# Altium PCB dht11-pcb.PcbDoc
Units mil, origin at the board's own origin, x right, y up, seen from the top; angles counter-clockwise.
Board outline 2115 x 2690 mil, 2 copper layers (Top Layer, Bottom Layer); 49 components, 31 nets, 189 pads, 153 vias.
Unrouted connection lines stored in the file: 35.
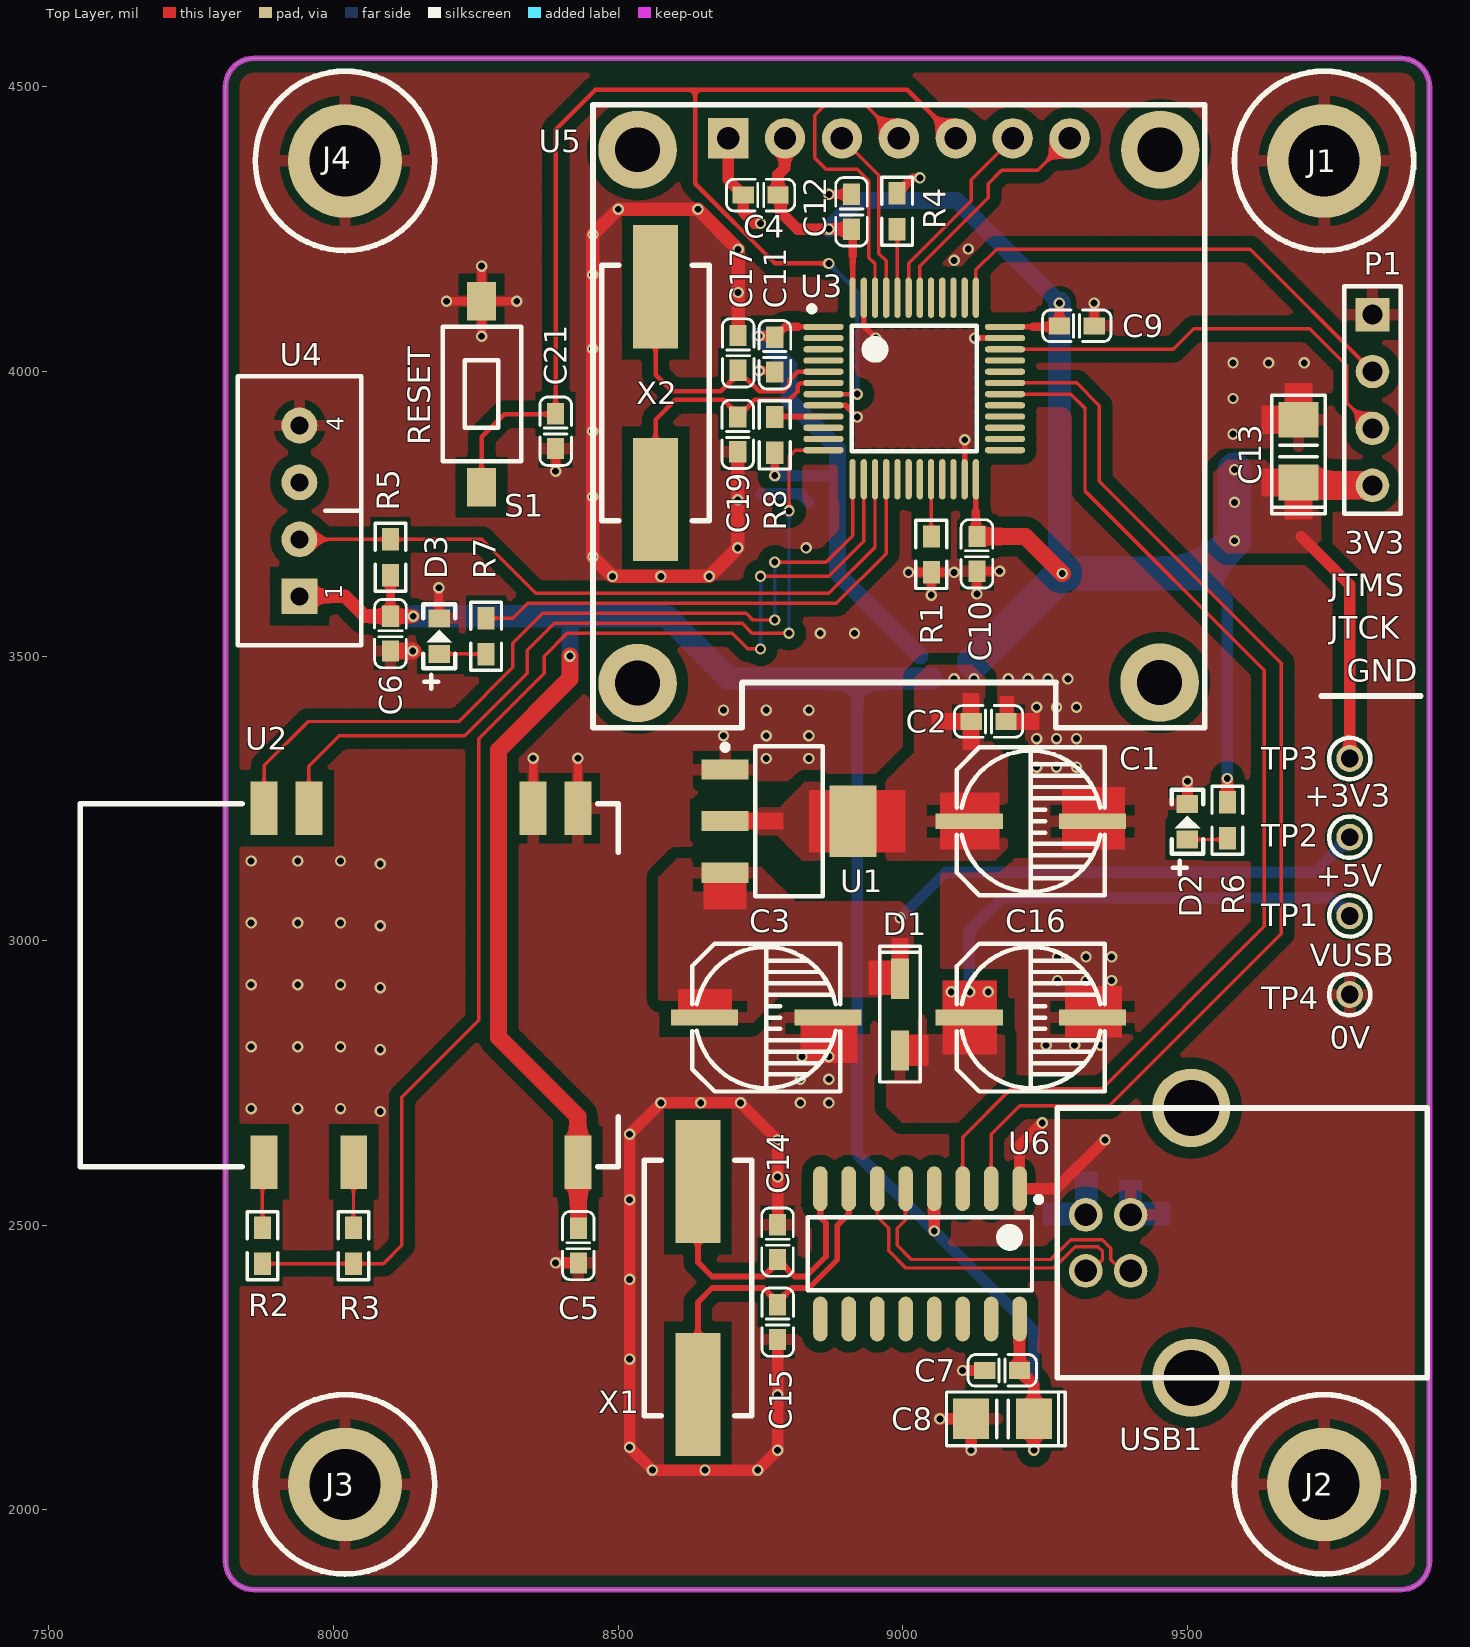
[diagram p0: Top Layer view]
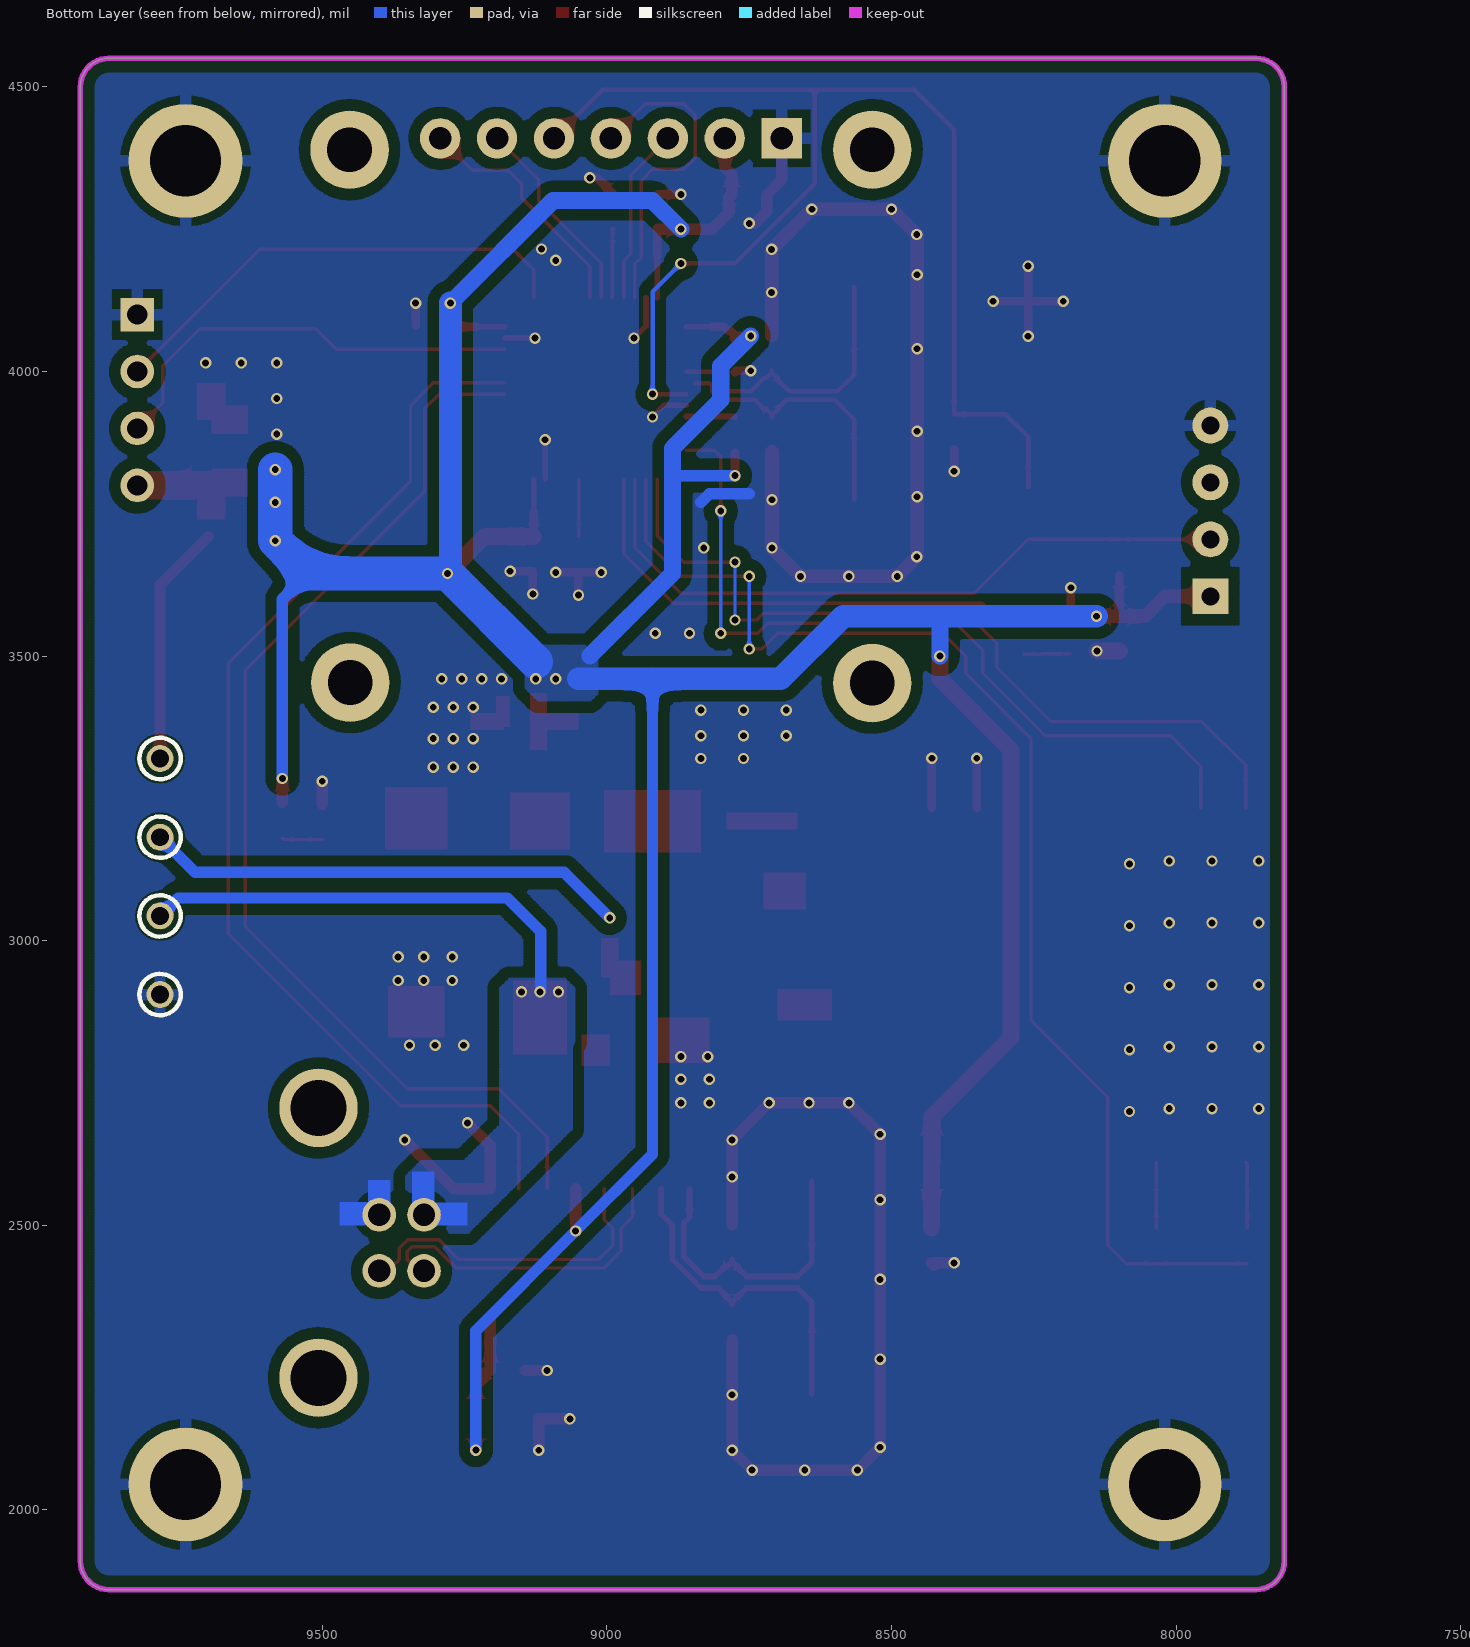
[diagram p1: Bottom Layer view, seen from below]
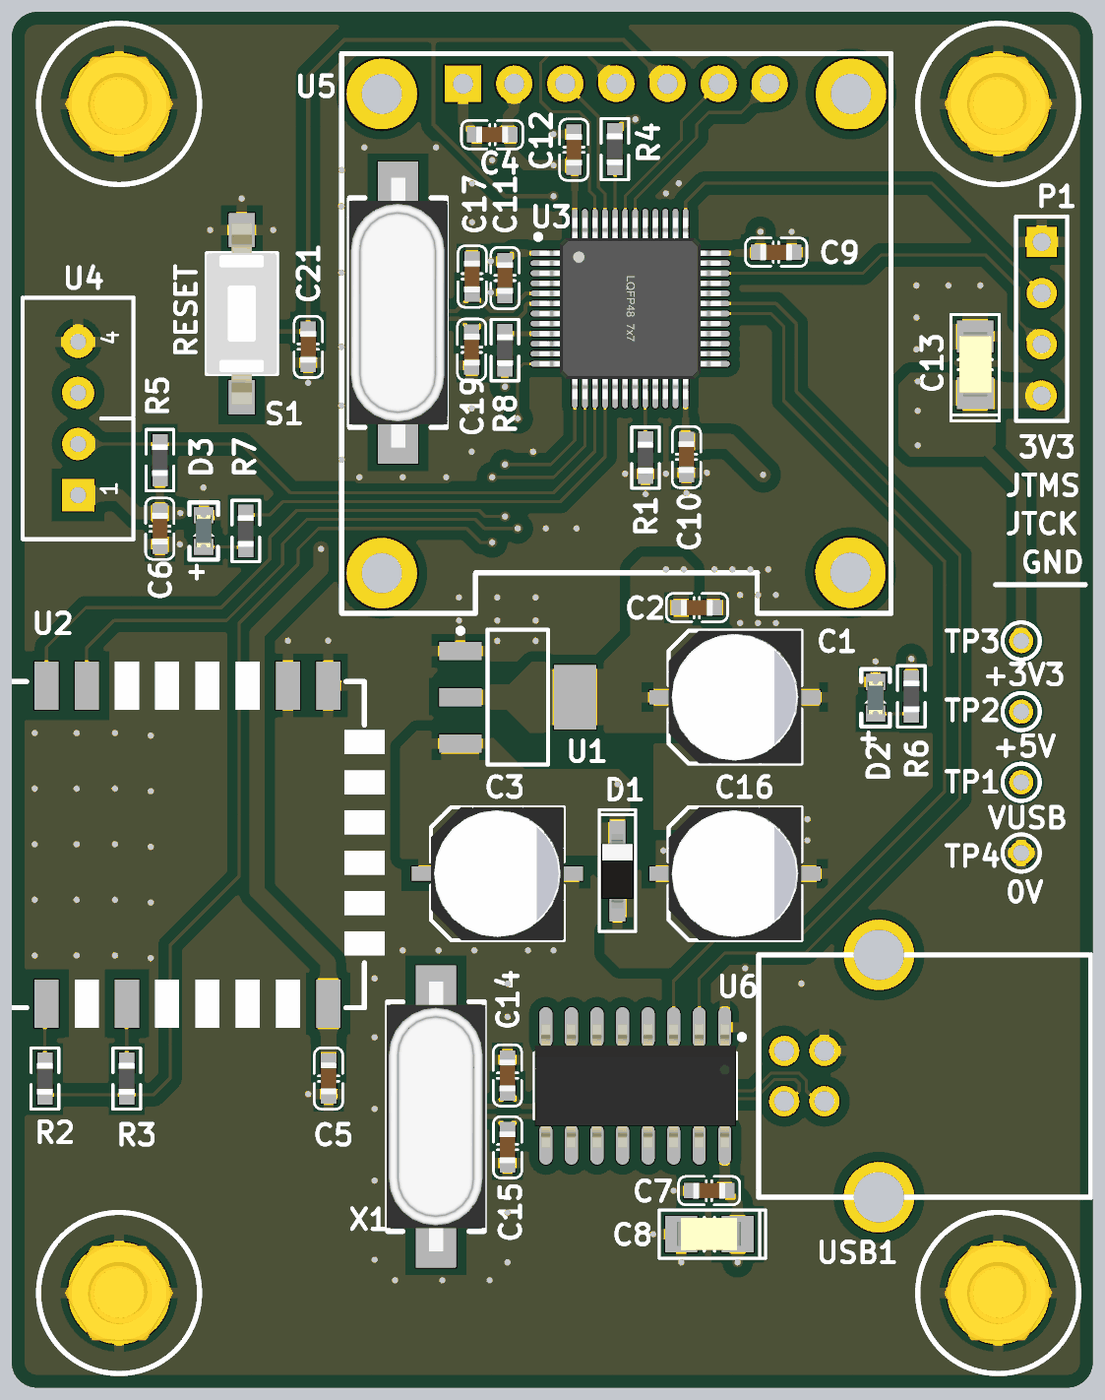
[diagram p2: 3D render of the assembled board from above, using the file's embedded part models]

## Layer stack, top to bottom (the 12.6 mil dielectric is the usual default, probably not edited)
Top Solder: solder mask 0.4, Solder Resist, Dk 3.5
Top Layer: signal copper 1.4
Dielectric 1: dielectric 12.6, FR-4, Dk 4.8
Bottom Layer: signal copper 1.4
Bottom Solder: solder mask 0.4, Solder Resist, Dk 3.5

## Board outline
7810,1910 7810,4500 cw(c7860,4500) 7860,4550 9875,4550 cw(c9875,4500) 9925,4500 9925,1910 cw(c9875,1910) 9875,1860 7860,1860 cw(c7860,1910)

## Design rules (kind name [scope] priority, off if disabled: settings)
Clearance [All] p1: gap=6 ignorepadtopadclearanceinfootprint=TRUE except(10: Arc-Via Track-Via SMDPad-Via THPad-Via Via-Via; 20: Arc-Fill Arc-Poly Arc-Region Track-Fill Track-Poly Track-Region SMDPad-Fill SMDPad-Poly SMDPad-Region THPad-Fill THPad-Poly THPad-Region Via-Fill Via-Poly Via-Region Fill-Fill Fill-Poly Fill-Region Poly-Poly Poly-Region Region-Region)
PolygonConnect PolygonConnect_via [isvia] p1: connectstyle=Direct reliefconductorwidth=10 reliefentries=4 polygonreliefangle="90 Angle" airgapwidth=10
PolygonConnect [All] p2: connectstyle=Relief reliefconductorwidth=20 reliefentries=4 polygonreliefangle="90 Angle" airgapwidth=15
RoutingVias [All] p1: holewidth=12 width=24 viastyle="Through Hole" minholewidth=12 minwidth=24 maxholewidth=12 maxwidth=24
SolderMaskExpansion [All] p1: expansion=2.5
Width Width_POWER [InNetClass('POWER')] p1: maxlimit=60 minlimit=10 preferedwidth=15
Width [All] p2: maxlimit=10 minlimit=6 preferedwidth=6
30 further rules are at their usual default settings.

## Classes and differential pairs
net class MISC: LED0 NetC14_2 NetC15_2 NetD2_1 NetD3_1 NetR1_1 NetR2_2 NetR3_2 NetR4_1 NetR8_2 PA5/DATA WIFI_EN
net class USART: PA2/USART2_TXD PA3/USART2_RXD PA9/USART1_TXD PA10/USART1_RXD
net class OLED: OLED_CS OLED_D0 OLED_D1 OLED_DC
net class POWER: GND VCC_3V3 VCC_5V VCC_USB

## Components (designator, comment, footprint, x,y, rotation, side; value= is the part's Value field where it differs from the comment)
C1 "220uF" C_SMD(6.3x5.3) 9225,3210 r0 top
C2 "0.1uF" C0603 9150.51,3385 r180 top
C3 "220uF/10V" C_SMD(6.3x5.3) 8760,2865 r0 top
C4 "0.1uF" C0603 8750,4310 r0 top
C5 "0.1uF" C0603 8430,2464.49 r270 top
C6 "0.1uF" C0603 8100,3539.49 r270 top
C7 "0.1uF" C0603 9174.49,2245 r180 top
C8 "10uF" TAC1206 9175,2160 r180 top
C9 "0.1uF" C0603 9305.51,4080 r180 top
C10 "0.1uF" C0603 9130,3679.49 r90 top
C11 "0.1uF" C0603 8775,4029.49 r90 top
C12 "0.1uF" C0603 8910,4280.51 r270 top
C13 "10uF" TAC1206 9695,3860 r90 top
C14 "22pF" C0603 8780.02,2470.47 r270 top
C15 "22pF" C0603 8780.02,2329.96 r90 top
C16 "220uF/10V" C_SMD(6.3x5.3) 9225,2865 r0 top
C17 "22pF" C0603 8710.62,4032.46 r90 top
C19 "22pF" C0603 8710,3889.49 r270 top
C21 "0.1uF" C0603 8390,3895 r90 top
D1 "1N5819" SOD123 8995,2870 r90 top
D2 "LED" LED_0603 9500,3208.9 r90 top
D3 "LED" LED_0603 8185.69,3535 r90 top
J1 "Hole-3mmx6mm" M3x7+6_L 9740,4370 r0 top
J2 "Hole-3mmx6mm" M3x7+6_L 9740,2045 r0 top
J3 "Hole-3mmx6mm" M3x7+6_L 8020,2045 r0 top
J4 "Hole-3mmx6mm" M3x7+6_L 8020,4370 r0 top
P1 "Download" HDR1X4 9825,4099.88 r270 top
R1 "10K" R0603 9050,3678.5 r270 top
R2 "1K" R0603 7875,2464.19 r90 top
R3 "1K" R0603 8035,2464.19 r90 top
R4 "10K" R0603 8990,4281.5 r90 top
R5 "4K7" R0603 8100,3673.5 r270 top
R6 "1K" R0603 9570,3211.5 r270 top
R7 "1K" R0603 8268,3535 r270 top
R8 "0R" R0603 8775,3888.5 r90 top
S1 "SW-PB" "micro button_2_SMD" 8260,3960 r90 top
TP1 "VUSB" TP 9785,3043.56 r270 top
TP2 "+5V" TP 9785,3181.78 r270 top
TP3 "+3V3" TP 9785,3320 r270 top
TP4 "0V" TP 9785,2905.34 r270 top
U1 "AMS1117-3v3" SOT223_L 8800,3210 r0 top
U2 "ESP8266" ESP8266 8429.13,3240.59 r270 top
U3 "STM32F103C8T6" "LQFP48 7X7_N" 9020,3970 r270 top
U4 "DHT11" DHT11 7940,3755 r90 top
U5 "OLED_0R96" OLED_0.96_SPI 8993,3931 r0 top locked
U6 "CH340" SOIC_16 9030,2450 r270 top
USB1 "USB-B" USB-B 9321.26,2420 r90 top
X1 "12MHz" HC-49SMD 8640,2390 r90 top
X2 "8MHz" HC-49SMD 8565.62,3961.95 r90 top

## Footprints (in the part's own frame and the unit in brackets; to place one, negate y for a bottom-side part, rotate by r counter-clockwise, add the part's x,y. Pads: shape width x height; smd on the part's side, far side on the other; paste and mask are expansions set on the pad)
C0603 [mm] "Chip Capacitor, 2-Leads, Body 1.6x0.8mm, IPC Medium Density"
  rect 0.95x0.762 smd: 1(-0.775,0) 2(0.775,0)
  silkscreen extent -1.53,-0.71 1.53,0.7, body extent -0.8,-0.4 0.8,0.4, height 0.6
C_SMD(6.3x5.3) [mm]
  rect 3x0.7 smd: 1(-2.75,0) 2(2.75,0)
  silkscreen extent -3.3,-3.3 3.3,3.3, body extent -3.3,-3.3 3.3,3.3, height 5.42
DHT11 [mm]
  rect 1.6x1.6 hole 0.8: 1(-3.81,0)
  round 1.6 hole 0.8: 2(-1.27,0) 3(1.27,0) 4(3.81,0)
  silkscreen extent -6,-2.75 6,2.75
ESP8266 [mm]
  rect 2.4x1.2 smd: 1(0.2,0) 2(0.2,-2) 7(0.2,-12) 8(0.2,-14) 9(16,-14) 11(16,-10) 16(16,0)
  rect 2.4x1.2 on Top Overlay: 3(0.2,-4) 4(0.2,-6) 5(0.2,-8) 6(0.2,-10) 10(16,-12) 12(16,-8) 13(16,-6) 14(16,-4) 15(16,-2)
  rect 1.2x2 on Top Overlay: 17(13,1.8) 18(11,1.8) 19(9,1.8) 20(7,1.8) 21(5,1.8) 22(3,1.8)
  silkscreen extent 0,-22.2 16.2,1.8
HC-49SMD [mm]
  rect 5.5x2 smd: 1(-4.75,0) 2(4.75,0)
  silkscreen extent -5.7,-2.4 5.7,2.4, body extent -6.7,-2.46 6.7,2.44, height 4
HDR1X4 [mm] "Connector; Header; 4 Position"
  rect 1.5x1.5 hole 0.9: 1(0,0)
  round 1.5 hole 0.9: 2(2.54,0) 3(5.08,0) 4(7.62,0)
  silkscreen extent -1.27,-1.27 8.89,1.27
LED_0603 [mm]
  rect 0.8x0.96 smd: 1(-0.79,0) 2(0.79,0)
  silkscreen extent -2.35,-0.71 1.42,0.71, body extent -0.81,-0.4 0.81,0.4, height 0.6
"LQFP48 7X7_N" [mm] "7*7*1.4(长宽高，除引脚）"
  oval 0.279x1.8 smd: 1(-2.75,-4.05) 2(-2.25,-4.05) 3(-1.75,-4.05) 4(-1.25,-4.05) 5(-0.75,-4.05) 6(-0.25,-4.05) 7(0.25,-4.05) 8(0.75,-4.05) 9(1.25,-4.05) 10(1.75,-4.05) 11(2.25,-4.05) 12(2.75,-4.05) 25(2.75,4.05) 26(2.25,4.05) 27(1.75,4.05) 28(1.25,4.05) 29(0.75,4.05) 30(0.25,4.05) 31(-0.25,4.05) 32(-0.75,4.05) 33(-1.25,4.05) 34(-1.75,4.05) 35(-2.25,4.05) 36(-2.75,4.05)
  oval 1.8x0.279 smd: 13(4.05,-2.75) 14(4.05,-2.25) 15(4.05,-1.75) 16(4.05,-1.25) 17(4.05,-0.75) 18(4.05,-0.25) 19(4.05,0.25) 20(4.05,0.75) 21(4.05,1.25) 22(4.05,1.75) 23(4.05,2.25) 24(4.05,2.75) 37(-4.05,2.75) 38(-4.05,2.25) 39(-4.05,1.75) 40(-4.05,1.25) 41(-4.05,0.75) 42(-4.05,0.25) 43(-4.05,-0.25) 44(-4.05,-0.75) 45(-4.05,-1.25) 46(-4.05,-1.75) 47(-4.05,-2.25) 48(-4.05,-2.75)
  silkscreen extent -3.68,-4.7 2.79,2.79, body extent -4.5,-4.5 4.5,4.5, height 1.45
M3x7+6_L [mil] "M3铜柱，长：7mm，螺纹长：6mm"
  round 200 hole 125: 1(0,0)
  silkscreen extent -157,-157 157,157, body extent -106,-93 106,93, height 278
"micro button_2_SMD" [mm]
  rect 1.7x1.3 smd: 1(-4.15,0) 2(4.15,0)
  silkscreen extent -3,-1.76 3,1.74, body extent -4.5,-1.75 4.5,1.75, height 4.51
OLED_0.96_SPI [mm] "GND、VCC、SCL、SDA"
  round 3.5 hole 2 mask+0.102: 0(-11.659,-12.154) 0(-11.659,11.646) 0(11.633,-12.128) 0(11.659,11.646)
  rect 1.8x1.8 hole 1 mask+0.102: 1(-7.62,12.154)
  round 1.8 hole 1 mask+0.102: 2(-5.08,12.154) 3(-2.54,12.154) 4(0,12.154) 5(2.54,12.154) 6(5.08,12.154) 7(7.62,12.154)
  silkscreen extent -13.65,-14.15 13.65,13.65
R0603 [mm] "Chip Resistor, 2-Leads, Body 1.6x0.8mm, IPC Medium Density"
  rect 1x0.762 smd: 1(-0.8,0) 2(0.8,0)
  silkscreen extent -1.52,-0.69 1.52,0.69, body extent -0.8,-0.4 0.8,0.4, height 0.38
SOD123 [mm]
  rect 1.8x0.8 smd: 1(-1.6,0) 2(1.6,0)
  silkscreen extent -3,-0.9 3.05,0.9, body extent -1.85,-0.8 1.85,0.8, height 1.27
SOIC_16 [mm]
  oval 2x0.65 smd: 1(-2.906,4.445) 2(-2.906,3.175) 3(-2.906,1.905) 4(-2.906,0.635) 5(-2.906,-0.635) 6(-2.906,-1.905) 7(-2.906,-3.175) 8(-2.906,-4.445) 9(2.906,-4.445) 10(2.906,-3.175) 11(2.906,-1.905) 12(2.906,-0.635) 13(2.906,0.635) 14(2.906,1.905) 15(2.906,3.175) 16(2.906,4.445)
  silkscreen extent -2.55,-5 1.63,5.42, body extent -3.06,-5 3.06,5, height 1.48
SOT223_L [mm] "SOT223, 4-Leads, Body 6.5x3.5mm, Pitch 2.3mm, Lead Span 7mm, IPC High Density"
  rect 2.1x0.9 smd: 1(-2.85,2.3) 2(-2.85,0) 3(-2.85,-2.3)
  rect 2.1x3.2 smd: 4(2.85,0)
  silkscreen extent -2.97,-3.35 1.5,3.42, body extent -1.85,-3.35 1.85,3.35, height 1.7
TAC1206 [mm]
  rect 1.6x1.8 smd: 1(-1.4,0) 2(1.4,0)
  silkscreen extent -2.79,-1.2 2.5,1.2, body extent -1.56,-0.81 1.61,0.79, height 1.77
TP [mm]
  round 1.2 hole 0.8: 1(0,0)
  silkscreen extent -0.92,-0.92 0.92,0.92
USB-B [mm]
  round 3.5 hole 2.5: 0(-4.77,-4.71) 0(7.27,-4.71)
  round 1.5 hole 1: 1(2.5,0) 2(0,0) 3(0,-2) 4(2.5,-2)
  silkscreen extent -4.77,-15.24 7.27,1.27

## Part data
C1 C3 C16: library part Cap3, "CAP ALUM POLY 150UF 20% 10V SMD", ESR (Equivalent Series Resistance)="22 mOhm", Lifetime @ Temp.="2000 Hrs @ 105°C", Manufacturer=KEMET, Manufacturer Part Number=A765EB157M1ALAE022, Operating Temperature="-55°C ~ 105°C", Package / Case="Radial, Can - SMD", Ratings=-, Supplier Part Number 1=399-13671-1-ND, Tolerance=±20%
C2 C4 C5 C6 C7 C9 C10 C11 C12 C14 C15 C17 C19 C21: library part Cap1, "CAP CER 10000PF 100V X7R 0603", Manufacturer="TDK Corporation", Manufacturer Part Number=C1608X7R2A103K080AA, Operating Temperature="-55°C ~ 125°C", Package / Case="0603 (1608 Metric)", Ratings=-, Supplier Part Number 1=445-1304-2-ND, Temperature Coefficient=X7R, Tolerance=±10%, Voltage - Rated=100V
C8 C13: library part Cap2, "CAP TANT 10UF 10V 10% 1206", ESR (Equivalent Series Resistance)="3.8 Ohm", Lifetime @ Temp.="2000 Hrs @ 125°C", Manufacturer=KEMET, Manufacturer Part Number=T491A106K010AT7280, Manufacturer Size Code=A, Operating Temperature="-55°C ~ 125°C", Package / Case="1206 (3216 Metric)", Supplier Part Number 1=399-8268-2-ND, Tolerance=±10%
D1: library part Diode, "Default Diode"
D2 D3: "Typical RED GaAs LED"
J1 J2 J3 J4: library part HOLED
P1 USB1: library part "Header 4", "Header, 4-Pin"
R1 R2 R3 R4 R5 R6 R7 R8: library part R, "贴片电阻"
S1: "Switch"
TP1 TP2 TP3: library part TP+, "正测试环"
TP4: library part TP-, "负测试环"
U2: library part "ESP8266 Module"
U3: "ARM Cortex-M3 32-bit MCU, 64 KB Flash, 20 KB Internal RAM, 37 I/Os, 48-pin LQFP, -40 to 85 degC, Tray", I/Os (High Current)=37, Operating Frequency(F) (Processor speed) (MHz)=72, Supplier Part Number 1=497-6063-ND, Supply Voltage(Vcc) min (V)=2
U4: "GROVE TEMP/HUMIDITY SENSOR", Manufacturer="Seeed Technology Co., Ltd", Manufacturer Part Number=101020011, Supplier Part Number 1=1597-1124-ND
U5: library part OLED_7P_0R96
X1 X2: library part Crystal, "CRYSTAL 12.0000MHZ 18PF SMD", Frequency Stability=±50ppm, Frequency Tolerance=±20ppm, Load Capacitance=18pF, Manufacturer="Abracon LLC", Manufacturer Part Number=ABLS-12.000MHZ-B2-T, Operating Mode=Fundamental, Operating Temperature="-20°C ~ 70°C", Package / Case=HC-49/US, Ratings=-, Supplier Part Number 1=535-9067-2-ND

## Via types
v1: diameter 20, hole 12, Top Layer to Bottom Layer, tented both sides, 153 vias

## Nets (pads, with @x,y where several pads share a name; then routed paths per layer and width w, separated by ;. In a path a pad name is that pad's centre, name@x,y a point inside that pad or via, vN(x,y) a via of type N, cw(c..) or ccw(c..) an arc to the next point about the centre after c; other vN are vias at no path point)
D+: U6.5 USB1.3 | length 575
  Top Layer w6: U6.5 9005,2510 8990,2495 8990,2465 9015,2440 9260,2440 9295,2475 9350,2475 9365,2460 9365,2440 9371.26,2433.74 9371.9,2433.74 9385.64,2420 USB1.3
D-: U6.6 USB1.2 | length 576.9
  Top Layer w6: U6.6 8955,2515 8975,2495 8975,2455 9005,2425 9265,2425 9302.5,2462.5 9342.5,2462.5 9350.78,2454.22 9350.78,2440 9330.78,2420 USB1.2
GND: C1.2 C2.1 C3.2 C4.1 C5.2 C6.2 C7.2 C8.2 C9.1 C10.1 C11.1 C12.1 C13.2 C14.1 C15.1 C16.2 C17.2 C19.2 C21.1 D2.2 D3.2 J1.1 J2.1 J3.1 J4.1 P1.1 R1.2 R4.2 S1.2 TP4.1 U1.1 U2.1 U2.2 U3.8 U3.23 U3.35 U3.47 U4.4 U5.1 U6.1 USB1.4 | length 4966.8
  Top Layer w10: U3.8 8899.53,3940.47 v1(8920,3920) ; U3.47 8931.42,4079.67 v1(8952.5,4058.58) ; U3.23 v1(9108.58,3880) ; v1(9126.42,4058.58) U3.35
  Top Layer w15: v1(8185,3620) 8185,3566.79 D3.2 ; v1(8198.39,4123.39) S1.2 ; v1(8260,4061.77) S1.2 ; v1(8260,4185) S1.2 ; v1(8321.61,4123.39) S1.2 ; U2.2 v1(8350.39,3320.39) ; v1(8390,3824.53) C21.1@8390,3863.5 ; U2.1 v1(8429.13,3320.39) ; v1(8747.44,4001.25) 8772.73,4001.25 C11.1 ; v1(8870,4311.02) C12.1 ; R4.2 9017.01,4340 v1(9030,4340) ; v1(9010,3647.01) R1.2 ; v1(9050,3607.01) R1.2 ; v1(9090,3647.01) R1.2 ; v1(9130,3608.98) C10.1 v1(9170,3648.98) ; C9.1 v1(9336.02,4120)
  Top Layer w20: v1(8390,2433.98) C5.2 C5.2@8426.02,2430 ; U5.1 8693,4336.49 C4.1@8710.79,4318.7 ; C4.1 8719.49,4280.51 8740,4260 v1(8750,4260) ; C15.1 v1(8780.02,2105.02) v1(8745,2070) v1(8560,2070) v1(8520,2110) v1(8520,2660) v1(8575,2715) v1(8715,2715) v1(8780.02,2649.98) C14.1 ; v1(9065,2160) C8.2 ; v1(9105,2245) C7.2 ; v1(9119.88,2105) C8.2@9119.88,2159.88 ; v1(9245,2680) 9205,2640 U6.1 9269.43,2564.43 v1(9355,2650) ; D2.2 v1(9500,3280)
  Top Layer w24: C19.2 v1(8710,3690) v1(8660,3640) v1(8490,3640) 8455,3675 8455,4240 v1(8500,4285) v1(8640,4285) v1(8710.62,4214.38) C17.2
  Top Layer w30: C6.2 v1(8138.98,3508.98)
  Bottom Layer w20: 8750,3785 8820,3785 8835,3770
  other v1: 8652.5,2070 8780.02,2202.23 8520,2265 8520,2405 8520,2545 8780,2585 8082.05,2700 7855,2705 7937.05,2705 8012.05,2705 8645,2715 8820,2715 8870,2715 8820,2756.46 8870,2756.46 8822.73,2796.46 8870,2796.46 8082.05,2808.75 7855,2813.75 7937.05,2813.75 8012.05,2813.75 9251.73,2816.46 9301.73,2816.46 9346.73,2816.46 8082.05,2917.5 7855,2922.5 7937.05,2922.5 8012.05,2922.5 9271.73,2930 9321.73,2930 9366.73,2930 9271.73,2971.46 9321.73,2971.46 9366.73,2971.46 8082.05,3026.25 7855,3031.25 7937.05,3031.25 8012.05,3031.25 8082.05,3135 7855,3140 7937.05,3140 8012.05,3140 9235,3305 9270,3305 9305,3305 8760,3320 8835,3320 9235,3355 9270,3355 9305,3355 8685,3360 8760,3360 8835,3360 8685,3405 8760,3405 8835,3405 9235,3410 9270,3410 9305,3410 9185,3460 9220,3460 9255,3460 9290,3460 8855,3540 8915,3540 8575,3640 8455.6,3674.4 8830,3690 8710,3774.49 8455,3780 9580,3890 8455,3895 9580,3952.5 9580,4015 9642.5,4015 9705,4015 8455,4040 8710.62,4138.68 8455,4170 9090,4195 9115,4215 8455.6,4240.6
JTCK: P1.2 U3.37 | length 849.9
  Top Layer w6: U3.37 9128.27,4178.27 9165,4215 9609.88,4215 P1.2
JTMS: P1.3 U3.34 | length 771.2
  Top Layer w6: U3.34 9475,4038.9 9511.1,4075 9715,4075 9779.94,4010.06 9779.94,3944.94 P1.3
LED0: R7.1 U3.16 | length 880.4
  Top Layer w6: R7.1 8315,3566.5 8341,3592.5 8883.29,3592.5 8970.79,3680 U3.16
NetC14_2: C14.2 U6.8 X1.2 | length 541.6
  Top Layer w10: X1.2 8640,2435 8665,2410 8755,2410 8770.02,2425.02 8770.02,2426.26 C14.2@8780.02,2436.26 ; C14.2 C14.2@8780.02,2436.26 ; U6.8 8855,2514 8865,2504 8865,2445 8830,2410 8809.98,2410 8793.72,2426.26 8790.02,2426.26 C14.2@8780.02,2436.26
NetC15_2: C15.2 U6.7 X1.1 | length 596.8
  Top Layer w10: X1.1 8640,2365 8665,2390 8755,2390 8770.02,2374.98 8770.02,2374.17 C15.2@8780.02,2364.17 ; C15.2 C15.2@8780.02,2364.17 ; U6.7 8905,2520 8885,2500 8885,2440 8835,2390 8805,2390 8790.02,2375.02 8790.02,2374.17 C15.2@8780.02,2364.17
NetD2_1: D2.1 R6.2 | length 70.9
  Top Layer w6: D2.1 9567.8,3177.8 R6.2
NetD3_1: D3.1 R7.2 | length 82.5
  Top Layer w6: D3.1 8236.2,3503.9 8236.59,3503.5 R7.2
NetR1_1: R1.1 U3.20 | length 100.7
  Top Layer w6: U3.20 9049.53,3710.47 R1.1
NetR2_2: R2.2 U2.9 | length 116.2
  Top Layer w6: R2.2 7875,2607.72 U2.9
NetR3_2: R3.2 U2.11 | length 115.2
  Top Layer w6: R3.2 8035,2610.24 U2.11
NetR4_1: R4.1 U3.44 | length 120.7
  Top Layer w6: U3.44 R4.1@8990.47,4249.53
  Top Layer w10: R4.1 R4.1@8990.47,4249.53
NetR8_2: R8.2 U3.9 | length 85.9
  Top Layer w10: R8.2 8775.79,3920.79 U3.9
NRST: C21.2 S1.1 U3.7 U5.5 | length 2269.9
  Top Layer w8: S1.1 8260,3885 8300,3925 8390,3925 C21.2 8390,4425 8460,4495 8635,4495 ; U3.7 v1(8919.84,3960.16) ; v1(8870,4189.69) 8775.31,4189.69 8635,4330 8635,4495 ; U5.5 9007.5,4495 8635,4495
  Bottom Layer w8: v1(8870,4189.69) 8919.84,4139.84 v1(8919.84,3960.16)
OLED_CS: U3.42 U5.7 | length 426.3
  Top Layer w6: U3.42 9029.84,4184.84 9150,4305 9150,4330 9173.25,4353.25 9236.75,4353.25 U5.7
OLED_D0: U3.45 U5.3 | length 312.3
  Top Layer w6: U5.3 8957.89,4344.61 8957.89,4207.11 8970.79,4194.21 U3.45
OLED_D1: U3.46 U5.4 | length 578.1
  Top Layer w6: U3.46 8951.1,4188.9 8940,4200 8940,4335 8920,4355 8865,4355 8845,4375 8845,4450 8865,4470 8932.5,4470 U5.4
OLED_DC: U3.43 U5.6 | length 355.8
  Top Layer w6: U3.43 9010.16,4190.16 9120,4300 9120,4336.5 U5.6
OSC_IN: C17.1 U3.5 X2.2 | length 514.1
  Top Layer w8: X2.2 8565.62,3994.38 8595,3965 8680,3965 8700.62,3985.62 8700.62,3988.25 C17.1@8710.62,3998.25 ; C17.1 C17.1@8710.62,3998.25 ; U3.5 8824.53,3999.53 8815.47,3999.53 8800.52,3984.57 8800.52,3975.52 8790,3965 8747.57,3965 8724.32,3988.25 8720.62,3988.25 C17.1@8710.62,3998.25
OSC_OUT: C19.1 U3.6 X2.1 | length 478.9
  Top Layer w8: X2.1 8565.62,3915.62 8600,3950 8685,3950 8700,3935 8700,3933.7 C19.1@8710,3923.7 ; C19.1 C19.1@8710,3923.7 ; U3.6@8845.16,3979.65 8819.96,3979.65 8815,3974.69 8815,3964.69 8800.31,3950 8740,3950 8723.7,3933.7 8720,3933.7 C19.1@8710,3923.7
PA2/USART2_TXD: U2.7 U3.12 | length 1427.6
  Top Layer w6: U2.7 7956.69,3306.69 8010,3360 8230,3360 8340,3470 8340,3510 8387.5,3557.5 8717.5,3557.5 8735,3540 v1(8800,3540) ; v1(8800,3755) 8800,3850.6 8811.13,3861.73 U3.12
  Bottom Layer w6: v1(8800,3540) v1(8800,3755)
PA3/USART2_RXD: U2.8 U3.13 | length 1467.5
  Top Layer w6: U2.8 7877.95,3307.95 7955,3385 8220,3385 8315,3480 8315,3522.5 8367.5,3575 8725,3575 8736.67,3563.33 v1(8775,3563.33) ; v1(8775,3665) 8865,3665 8911.73,3711.73 U3.13
  Bottom Layer w6: v1@8775,3565 v1(8775,3665)
PA5/DATA: R5.1 U3.15 U4.2 | length 1203.5
  Top Layer w6: U4.2 R5.1 8260,3705 8355,3610 8870,3610 8951.1,3691.1 U3.15
PA9/USART1_TXD: U3.30 U6.3 | length 1965.3
  Top Layer w6: U6.3 9105,2655 9190,2740 9350,2740 9635,3025 9635,3475 9320,3790 9320,3935 9294.84,3960.16 U3.30
PA10/USART1_RXD: U3.31 U6.2 | length 1993.6
  Top Layer w6: U6.2 9155,2660 9205,2710 9362.43,2710 9665,3012.57 9665,3487.43 9345,3807.43 9345,3940 9305.16,3979.84 U3.31
VCC_3V3: C1.1 C2.2 C4.2 C5.1 C6.1 C7.1 C8.1 C9.2 C10.2 C11.2 C12.2 C13.1 P1.4 R5.2 R6.1 R8.1 TP3.1 U1.2 U1.4 U2.16 U3.1 U3.24 U3.36 U3.48 U4.1 U5.2 U6.4 U6.16 | length 8614.7
  Top Layer w10: 8815.28,4078.27 U3.1 ; U3.48 8911.73,4203.27 ; 9128.27,3753.27 U3.24 ; U3.36 9228.27,4078.27
  Top Layer w15: C6.1 R5.2 ; v1(8747.44,4062.27) C11.2@8772.73,4062.27 ; v1(8775,3817.01) R8.1 ; C11.2@8777.51,4057.49 C11.2 8775,4063.7 8782.5,4071.2 8786.2,4071.2 8793.27,4078.27 8815.28,4078.27 ; C12.2 8911.73,4248.27 8911.73,4203.27 ; 9128.27,3753.27 9128.27,3711.73 C10.2 ; 9228.27,4078.27 9273.27,4078.27 C9.2 v1(9275,4120)
  Top Layer w20: U2.16 U2.16@8430,2609.8 ; U5.2 8792.48,4408.98 8792.48,4357.48 8780.51,4345.51 C4.2 8780.82,4310 8785.82,4305 8785.82,4279.18 8815,4250 v1(8870,4250) C12.2 ; v1(9055,2490) U6.4 ; U6.16 C7.1 9208.7,2245 9213.7,2240 9213.7,2236.3 9230,2220 9230,2160.12 C8.1 v1(9230.12,2105.12) ; R6.1 v1(9570,3285) ; 9700,3710 9785,3625 TP3.1
  Top Layer w24: U4.1 8020,3605 8055,3570 C6.1 v1(8140,3570)
  Top Layer w30: v1(8415,3500) 8415,3460 8290,3335 8290,2830 8429.13,2690.87 U2.16 ; C5.1 U2.16@8430,2609.8 ; C10.2 9215,3710 v1(9280,3645) ; C13.1 C13.1@9700,3799.88
  Top Layer w50: C13.1@9700,3799.88 P1.4
  Bottom Layer w20: v1(8775,3817.01) 8882.99,3817.01 ; 8920,3460 8920,2625 v1(9055,2490) 9230.12,2314.88 v1(9230.12,2105.12) ; v1@9275,3650 v1(9280,3645) ; 9525,3645 9570,3600 v1(9570,3285)
  Bottom Layer w30: v1(8415,3500) 8415,3570 ; v1(8747.44,4062.27) 8800,4009.71 8800,3950 8885,3865 8885,3645 9030,3500 ; v1(8870,4250) 8920,4300 9095,4300 v1(9275,4120)
  Bottom Layer w40: v1(8140,3570) 8415,3570 8585,3570 8695,3460 8920,3460 9050,3460 ; v1@9275,3650 v1(9275,4120)
  Bottom Layer w60: 9125,3490 v1(9280,3645) 9525,3645 v1(9582.5,3702.5) v1(9582.5,3827.5)
  other v1: 9090,3460 9125,3460 9582.5,3770
VCC_5V: C3.1 D1.2 TP2.1 U1.3 | length 848.7
  Bottom Layer w20: v1(8995,3040) 9075,3120 9723.22,3120 TP2.1
VCC_USB: C16.1 D1.1 TP1.1 USB1.1 | length 812.7
  Bottom Layer w20: v1(9117.5,2910) 9116.46,2911.04 9116.46,3016.46 9175,3075 9753.56,3075 TP1.1
  other v1: 9085,2910 9150,2910
WIFI_EN: R2.1 R3.1 U3.14 | length 2248.4
  Top Layer w6: R2.1 R3.1 8087.69,2432.69 8120,2465 8120,2725 8255,2860 8255,3355 8370,3470 8370,3500 8410,3540 8700,3540 8727.5,3512.5 v1(8750,3512.5) ; v1(8750,3640) 8870,3640 8931.42,3701.42 U3.14
  Bottom Layer w6: v1(8750,3512.5) v1(8750,3640)
pads on no net: U2.3 U2.4 U2.5 U2.6 U2.10 U2.12 U2.13 U2.14 U2.15 U2.17 U2.18 U2.19 U2.20 U2.21 U2.22 U3.2 U3.3 U3.4 U3.10 U3.11 U3.17 U3.18 U3.19 U3.21 U3.22 U3.25 U3.26 U3.27 U3.28 U3.29 U3.32 U3.33 U3.38 U3.39 U3.40 U3.41 U4.3 U5.0 U6.9 U6.10 U6.11 U6.12 U6.13 U6.14 U6.15 USB1.0

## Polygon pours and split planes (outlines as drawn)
GND on Top Layer "GND_L01_P034" (hatched 90Degree grid 5 track 10, remove dead copper, pour order 34): 7810,1910 7810,4500 cw(c7860,4500) 7860,4550 9875,4550 cw(c9875,4500) 9925,4500 9925,1910 cw(c9875,1910) 9875,1860 7860,1860 cw(c7860,1910)
GND on Top Layer "GND_L01_P028" (hatched 90Degree grid 5 track 10, remove dead copper, pour order 28): 8645,3285 8645,3415 8685,3455 8860,3455 8900,3415 8900,3320 8865,3285
GND on Top Layer "GND_L01_P024" (hatched 90Degree grid 5 track 10, remove dead copper, pour order 24): 9160,3370 9210,3370 9225,3355 9225,3170 9255,3140 9375,3140 9395,3160 9395,3290 9315,3370 9315,3460 9290,3485 9190,3485 9160,3455
VCC_3V3 on Top Layer "VCC_3V3_L01_P022" (hatched 90Degree grid 5 track 10, remove dead copper, pour order 22): 8645,3230 8785,3230 8830,3275 8970,3275 9025,3330 9025,3460 9045,3480 9120,3480 9140,3460 9140,3360 9180,3320 9180,3165 9160,3145 8825,3145 8780,3190 8645,3190
GND on Top Layer "GND_L01_P018" (hatched 90Degree grid 5 track 10, remove dead copper, pour order 18): 9395,2995 9395,2835 9355,2795 9235,2795 9225,2805 9225,2960 9260,2995
GND on Top Layer "GND_L01_P014" (hatched 90Degree grid 5 track 10, remove dead copper, pour order 14): 8817.5,2692.5 8917.5,2692.5 8930,2705 8930,2880 8805,2880 8805,2705
VCC_5V on Top Layer "VCC_5V_L01_P008" (hatched 90Degree grid 5 track 10, remove dead copper, pour order 8): 8725,2850 8780,2905 9005,2905 9015,2915 9015,3045 8995,3065 8810,3065 8735,3140 8605,3140 8575,3110 8575,2850
VCC_USB on Top Layer "VCC_L02_P-001" (hatched 90Degree grid 5 track 10, remove dead copper, pour order 4): 9175,2880 9050,2880 9015,2845 8975,2845 8975,2710 9000,2685 9100,2685 9175,2760
VCC_3V3 on Top Layer "VCC_3V3_L01_P002" (hatched 90Degree grid 5 track 10, remove dead copper, pour order 2): 9730,3840 9730,3705 9710,3685 9570,3685 9550,3705 9550,3820 9570,3840
GND on Top Layer "GND_L01_P000" (hatched 90Degree grid 5 track 10, remove dead copper, pour order 0): 9730,3880 9730,4015 9710,4035 9570,4035 9550,4015 9550,3900 9570,3880
GND on Top Layer "GND_L01_P016" (hatched 90Degree grid 5 track 10, remove dead copper, pour order 16): 9275,2855
GND on Top Layer "GND_L01_P012" (hatched 90Degree grid 5 track 10, remove dead copper, pour order 12): 8805,2900
GND on Top Layer "GND_L01_P010" (hatched 90Degree grid 5 track 10, remove dead copper, pour order 10): 8780,2815
GND on Bottom Layer "VCC_L02_P-001" (hatched 90Degree grid 5 track 10, remove dead copper, pour order 29): 7810,1910 7810,4500 cw(c7860,4500) 7860,4550 9875,4550 cw(c9875,4500) 9925,4500 9925,1910 cw(c9875,1910) 9875,1860 7860,1860 cw(c7860,1910)
VCC_USB on Bottom Layer "VCC_USB_L02_P006" (hatched 90Degree grid 5 track 10, remove dead copper, pour order 6): 9245,2490 9060,2675 9060,2915 9075,2930 9170,2930 9185,2915 9185,2675 9250,2610 9325,2610 9350,2585 9350,2490
VCC_3V3 on Bottom Layer "VCC_3V3_L02_P026" (hatched 90Degree grid 5 track 10, remove dead copper, pour order 26): 9020,3435 9020,3495 9040,3515 9120,3515 9140,3495 9140,3445 9120,3425 9030,3425
GND on Bottom Layer "GND_L02_P020" (hatched 90Degree grid 5 track 10, remove dead copper, pour order 20): 9220,3000 9385,3000 9415,2970 9415,2665 9490,2590 9490,2500 9475,2485 9395,2485 9380,2500 9380,2595 9340,2635 9265,2635 9220,2680

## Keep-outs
Keep-Out Layer:
  lines w10: 7810,1910 ccw(c7860,1910) 7860,1860 9875,1860 ccw(c9875,1910) 9925,1910 9925,4500 ccw(c9875,4500) 9875,4550 7860,4550 ccw(c7860,4500) 7810,4500 7810,4365 7810,1910

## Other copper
Top Layer:
  rectangle net GND: 9280,3160 9390,3270
  rectangle net GND: 9170,3375 9195,3430
  rectangle net GND: 9181.02,3370 9240,3400
  rectangle net VCC_3V3: 9050,3370 9120,3400
  rectangle net VCC_3V3: 9105,3335 9135,3435
  rectangle net VCC_3V3: 9065,3160 9170,3260
  rectangle net VCC_3V3: 8835,3155 9005,3265
  rectangle net VCC_3V3: 8665,3195 8790,3225
  rectangle net GND: 9285,2830 9385,2920
  rectangle net GND: 8820,2785 8920,2865
  rectangle net VCC_5V: 8980,2935 9010,3005
  rectangle net VCC_5V: 8940,2905 8995,2965
  rectangle net VCC_5V: 8605,2860 8700,2915
  rectangle net VCC_5V: 8650,3055 8725,3119.45
  rectangle net VCC_USB: 8995,2780 9045,2835
  rectangle net VCC_USB: 9070,2865 9165,2930
  rectangle net VCC_USB: 9070,2800 9165,2865
  region net VCC_3V3: 9720,3804.88 9670,3804.88 9670,3740 9720,3740
  region net VCC_3V3: 9695,3779.88 9695,3829.88 9630.12,3829.88 9630.12,3779.88
  region net GND: 9695,3890.12 9695,3940.12 9630.12,3940.12 9630.12,3890.12
  rectangle net GND: 9670,3915.12 9720,3980
  pour cut-out: 8635,4480 8835,4480 8905,4410 9085,4410 9125,4370 9125,4280 9085,4240 8859.14,4240 8820,4200.86 8764.14,4200.86 8635,4330
  pour cut-out: 8638.24,2841.43 8746.43,2841.43 8785,2880 8925,2880 8970,2835 9060,2835 9070,2845 9070,3115 9045,3140 9220,3140 9225,3145 9225,3345 9235,3355 9022.48,3355 8957.48,3290 8665,3290 8630,3255 8630,3150 8645,3135 8645,2840.33 8639.67,2835
Bottom Layer:
  rectangle net GND: 9380,2515 9420,2580
  rectangle net GND: 9400,2500 9470,2540.69
  region net VCC_USB: 9302.83,2594.68 9302.83,2514.68 9342.83,2514.68 9342.83,2594.68
  rectangle net VCC_USB: 9245,2500 9325,2540

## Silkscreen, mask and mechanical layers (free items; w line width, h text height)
Top Overlay:
  lines w10: 9735,3430 9910,3430
  text "RESET" at 8170,3870 h40 r90
  text "3V3" at 9775,3680 h40
  text "JTMS" at 9750,3605 h40
  text "JTCK" at 9750,3530 h40
  text "GND" at 9780,3455 h40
